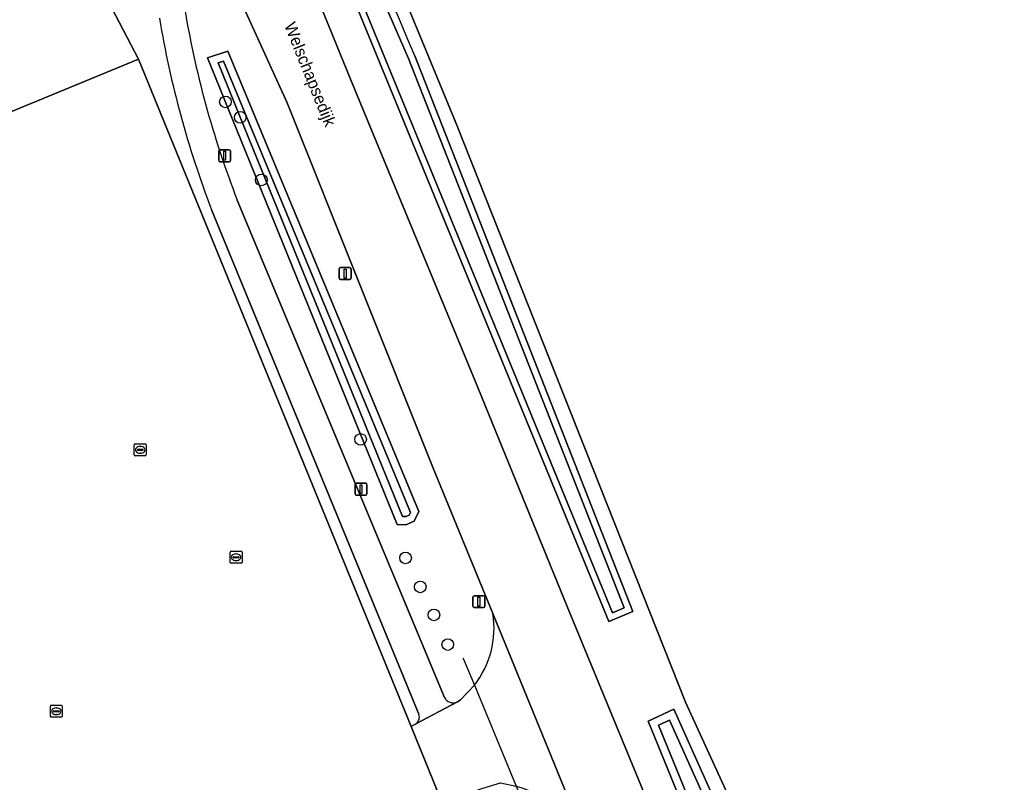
# Model space of a CAD drawing. Extents: x 156061 to 157804, y 383437 to 385640.
# Drawn here: x 157555.9 to 157638, y 383821.9 to 383885.9 of the extents above; entities that cross this region are included whole.
import ezdxf

# ---------------------------------------------------------------- set-up
doc = ezdxf.new("R2010")
doc.units = 0
for name, color, linetype in [('IMGEO_Boom', 7, 'Continuous'), ('IMGEO_Bouwland', 7, 'Continuous'), ('IMGEO_Duiker', 7, 'Continuous'), ('IMGEO_Erf', 7, 'Continuous'), ('IMGEO_Fietspad_gesloten', 7, 'Continuous'), ('IMGEO_Grasland_overig', 7, 'Continuous'), ('IMGEO_Groenvoorziening', 7, 'Continuous'), ('IMGEO_Hek', 7, 'Continuous'), ('IMGEO_Kolk', 7, 'Continuous'), ('IMGEO_Lichtmast', 7, 'Continuous'), ('IMGEO_Oever', 7, 'Continuous'), ('IMGEO_Openbare_ruimte_label', 7, 'Continuous'), ('IMGEO_Rijbaan_lokaal_gesloten', 7, 'Continuous'), ('IMGEO_Waterloop', 7, 'Continuous')]:
    doc.layers.add(name, color=color, linetype=linetype)

msp = doc.modelspace()

# ---------------------------------------------------------------- linework, layer by layer
at = {"layer": 'IMGEO_Boom'}
for centre in [(157573.23, 383879.012), (157574.474, 383877.713), (157576.243, 383872.456), (157584.585, 383850.666), (157588.355, 383840.711), (157589.594, 383838.279), (157590.74, 383835.926), (157591.907, 383833.435)]:
    msp.add_circle(centre, 0.489, dxfattribs=at)
at = {"layer": 'IMGEO_Bouwland'}
msp.add_lwpolyline([(157569.269, 383927.726), (157571.61, 383923.119), (157579.364, 383907.864), (157588.089, 383888.129), (157592.659, 383877.063), (157611.861, 383828.593), (157620.267, 383810.258)], dxfattribs=at)
at = {"layer": 'IMGEO_Duiker'}
msp.add_lwpolyline([(157593.175, 383832.32), (157593.217, 383832.219), (157594.135, 383830.012), (157597.662, 383821.536), (157598.502, 383819.516), (157598.62, 383819.234)], dxfattribs=at)
at = {"layer": 'IMGEO_Erf'}
msp.add_lwpolyline([(157547.624, 383703.184), (157563.901, 383717.144), (157563.393, 383717.746), (157565.034, 383719.104), (157565.113, 383719.606), (157570.669, 383724.172), (157577.494, 383716.583), (157605.408, 383740.892), (157602.352, 383750), (157597.931, 383763.176), (157581.731, 383811.93), (157588.46, 383816.531), (157589.526, 383818.477), (157589.676, 383818.715), (157589.889, 383818.998), (157590.127, 383819.262), (157590.386, 383819.503), (157590.667, 383819.72), (157590.965, 383819.91), (157591.28, 383820.074), (157591.436, 383820.144), (157588.82, 383826.546), (157565.924, 383882.594), (157500, 383855.42)], dxfattribs=at)
at = {"layer": 'IMGEO_Fietspad_gesloten'}
for points in [[(157591.619, 383828.994), (157574.219, 383870.769)], [(157572.089, 383869.901), (157589.47, 383827.582)], [(157589.235, 383826.786), (157592.707, 383828.616)]]:
    msp.add_lwpolyline(points, dxfattribs=at)
for centre, radius, start, end in [((157650.226, 383900.279), 81.535, 189.27321, 201.21866), ((157649.02, 383899.57), 82.454, 189.44953, 201.08955), ((157592.361, 383829.374), 0.834, 207.15129, 294.53155), ((157588.84, 383827.335), 0.676, 305.71255, 21.39149)]:
    msp.add_arc(centre, radius, start, end, dxfattribs=at)
at = {"layer": 'IMGEO_Grasland_overig'}
msp.add_lwpolyline([(157500, 383855.42), (157565.924, 383882.594), (157562.422, 383889.314), (157554.173, 383911.134)], dxfattribs=at)
at = {"layer": 'IMGEO_Groenvoorziening'}
for points in [[(157555.936, 383937.978), (157567.649, 383916.146), (157574.443, 383902.797), (157575.841, 383901.417), (157579.951, 383892.187), (157580.13, 383890.352), (157580.203, 383889.6), (157583.743, 383880.908), (157594.173, 383855.636), (157601.935, 383836.642), (157610.744, 383815.241), (157612.747, 383810.251)], [(157709.127, 383838.303), (157708.901, 383838.826), (157708.521, 383839.482), (157702.798, 383849.357), (157707.546, 383840.384), (157700.202, 383834.337), (157695.919, 383830.811), (157693.54, 383829.055), (157691.043, 383827.496), (157689.841, 383826.746), (157683.073, 383823.26), (157676.592, 383820.429), (157634.606, 383803.387), (157626.262, 383803.732), (157620.267, 383810.258), (157611.861, 383828.593), (157592.659, 383877.063), (157588.089, 383888.129), (157579.364, 383907.864), (157571.61, 383923.119), (157569.269, 383927.726)], [(157554.173, 383911.134), (157562.422, 383889.314), (157565.924, 383882.594), (157588.82, 383826.546), (157589.235, 383826.786)], [(157589.126, 383882.867), (157607.436, 383836.202), (157605.427, 383835.371), (157584.115, 383887.329), (157576.317, 383905.276)], [(157595.701, 383836.038), (157590.677, 383848.249), (157578.419, 383878.917), (157574.359, 383887.856), (157574.182, 383887.793), (157573.057, 383889.421), (157569.032, 383898.551)], [(157574.219, 383870.769), (157591.619, 383828.994)], [(157589.47, 383827.582), (157572.089, 383869.901)], [(157592.707, 383828.616), (157592.966, 383828.799), (157594.135, 383830.012)], [(157614.914, 383811.856), (157608.724, 383827.011), (157610.885, 383827.994), (157618.869, 383810.192)]]:
    msp.add_lwpolyline(points, dxfattribs=at)
msp.add_lwpolyline([(157589.476, 383844.598), (157589.085, 383843.789), (157588.375, 383843.5), (157587.647, 383843.51), (157571.725, 383882.697), (157573.438, 383883.276)], close=True, dxfattribs=at)
for centre, radius, start, end in [((157159.809, 383704.268), 464.985, 22.5876, 28.70083), ((157650.226, 383900.279), 81.535, 189.27321, 201.21866), ((157649.02, 383899.57), 82.454, 189.44953, 201.08955), ((157587.907, 383834.847), 7.885, 322.17817, 8.68693), ((157592.361, 383829.374), 0.834, 207.15129, 294.53155), ((157588.84, 383827.335), 0.676, 305.71255, 21.39149)]:
    msp.add_arc(centre, radius, start, end, dxfattribs=at)
at = {"layer": 'IMGEO_Hek'}
for points in [[(157500, 383855.42), (157565.924, 383882.594)], [(157565.924, 383882.594), (157588.82, 383826.546)], [(157588.82, 383826.546), (157591.436, 383820.144)]]:
    msp.add_lwpolyline(points, dxfattribs=at)
at = {"layer": 'IMGEO_Kolk'}
for p, q in [((157565.576, 383849.361), (157565.576, 383850.213)), ((157565.651, 383850.287), (157566.503, 383850.287)), ((157565.835, 383849.781), (157565.835, 383849.793)), ((157566.273, 383849.744), (157565.875, 383849.744)), ((157565.878, 383849.83), (157566.276, 383849.83)), ((157566.064, 383850.067), (157566.089, 383850.067)), ((157566.319, 383849.793), (157566.319, 383849.781)), ((157566.577, 383850.213), (157566.577, 383849.361)), ((157566.503, 383849.287), (157565.651, 383849.287)), ((157566.087, 383849.507), (157566.062, 383849.507)), ((157573.624, 383840.338), (157573.624, 383841.19)), ((157573.699, 383841.264), (157574.551, 383841.264)), ((157573.883, 383840.758), (157573.883, 383840.77)), ((157574.321, 383840.721), (157573.923, 383840.721)), ((157573.926, 383840.807), (157574.324, 383840.807)), ((157574.112, 383841.044), (157574.137, 383841.044)), ((157574.367, 383840.77), (157574.367, 383840.758)), ((157574.625, 383841.19), (157574.625, 383840.338)), ((157574.551, 383840.264), (157573.699, 383840.264)), ((157574.135, 383840.484), (157574.11, 383840.484)), ((157558.523, 383827.403), (157558.523, 383828.255)), ((157558.598, 383828.329), (157559.45, 383828.329)), ((157558.782, 383827.823), (157558.782, 383827.835)), ((157559.22, 383827.786), (157558.822, 383827.786)), ((157558.825, 383827.872), (157559.223, 383827.872)), ((157559.011, 383828.109), (157559.036, 383828.109)), ((157559.266, 383827.835), (157559.266, 383827.823)), ((157559.524, 383828.255), (157559.524, 383827.403)), ((157559.45, 383827.329), (157558.598, 383827.329)), ((157559.034, 383827.549), (157559.009, 383827.549))]:
    msp.add_line(p, q, dxfattribs=at)
for points in [[(157565.576, 383849.361), (157565.576, 383850.213)], [(157565.651, 383850.287), (157566.503, 383850.287)], [(157566.577, 383850.213), (157566.577, 383849.361)], [(157566.503, 383849.287), (157565.651, 383849.287)], [(157573.624, 383840.338), (157573.624, 383841.19)], [(157573.699, 383841.264), (157574.551, 383841.264)], [(157574.625, 383841.19), (157574.625, 383840.338)], [(157574.551, 383840.264), (157573.699, 383840.264)], [(157558.523, 383827.403), (157558.523, 383828.255)], [(157558.598, 383828.329), (157559.45, 383828.329)], [(157559.524, 383828.255), (157559.524, 383827.403)], [(157559.45, 383827.329), (157558.598, 383827.329)]]:
    msp.add_lwpolyline(points, dxfattribs=at)
for centre, radius, start, end in [((157565.653, 383850.211), 0.0765, 91.55205, 178.44795), ((157565.653, 383850.211), 0.0765, 91.55205, 178.44795), ((157565.875, 383849.79), 0.0403, 85.87752, 175.75265), ((157565.872, 383849.78), 0.0366, 178.93798, 274.71019), ((157566.276, 383849.787), 0.043, 264.86636, 352.45326), ((157566.28, 383849.792), 0.0386, 1.73085, 96.63898), ((157566.501, 383850.211), 0.0765, 1.55205, 88.44795), ((157566.501, 383850.211), 0.0765, 1.55205, 88.44795), ((157565.653, 383849.363), 0.0765, 181.55205, 268.44795), ((157565.653, 383849.363), 0.0765, 181.55205, 268.44795), ((157566.501, 383849.363), 0.0765, 271.55205, 358.44795), ((157566.501, 383849.363), 0.0765, 271.55205, 358.44795), ((157573.701, 383841.188), 0.0765, 91.55205, 178.44795), ((157573.701, 383841.188), 0.0765, 91.55205, 178.44795), ((157573.923, 383840.767), 0.0403, 85.87752, 175.75265), ((157573.92, 383840.757), 0.0366, 178.93798, 274.71019), ((157574.324, 383840.764), 0.043, 264.86636, 352.45326), ((157574.328, 383840.769), 0.0386, 1.73085, 96.63898), ((157574.549, 383841.188), 0.0765, 1.55205, 88.44795), ((157574.549, 383841.188), 0.0765, 1.55205, 88.44795), ((157573.701, 383840.34), 0.0765, 181.55205, 268.44795), ((157573.701, 383840.34), 0.0765, 181.55205, 268.44795), ((157574.549, 383840.34), 0.0765, 271.55205, 358.44795), ((157574.549, 383840.34), 0.0765, 271.55205, 358.44795), ((157558.6, 383828.253), 0.0765, 91.55205, 178.44795), ((157558.6, 383828.253), 0.0765, 91.55205, 178.44795), ((157558.822, 383827.832), 0.0403, 85.87752, 175.75265), ((157558.819, 383827.822), 0.0366, 178.93798, 274.71019), ((157559.223, 383827.829), 0.043, 264.86636, 352.45326), ((157559.227, 383827.834), 0.0386, 1.73085, 96.63898), ((157559.448, 383828.253), 0.0765, 1.55205, 88.44795), ((157559.448, 383828.253), 0.0765, 1.55205, 88.44795), ((157558.6, 383827.405), 0.0765, 181.55205, 268.44795), ((157558.6, 383827.405), 0.0765, 181.55205, 268.44795), ((157559.448, 383827.405), 0.0765, 271.55205, 358.44795), ((157559.448, 383827.405), 0.0765, 271.55205, 358.44795)]:
    msp.add_arc(centre, radius, start, end, dxfattribs=at)
for centre, major_axis, ratio, start_param, end_param in [((157566.063, 383849.787), (-0.387, 0.002), 0.722429, 4.712389, 7.853982), ((157566.088, 383849.787), (-0.39, 0.002), 0.717154, 1.570796, 4.712389), ((157574.111, 383840.764), (-0.387, 0.002), 0.722429, 4.712389, 7.853982), ((157574.136, 383840.764), (-0.39, 0.002), 0.717154, 1.570796, 4.712389), ((157559.01, 383827.829), (-0.387, 0.002), 0.722429, 4.712389, 7.853982), ((157559.035, 383827.829), (-0.39, 0.002), 0.717154, 1.570796, 4.712389)]:
    msp.add_ellipse(centre, major_axis=major_axis, ratio=ratio, start_param=start_param, end_param=end_param, dxfattribs=at)
at = {"layer": 'IMGEO_Lichtmast'}
for p, q in [((157572.664, 383874.086), (157572.664, 383874.886)), ((157572.664, 383874.886), (157572.664, 383874.086)), ((157572.764, 383874.986), (157573.554, 383874.986)), ((157573.554, 383874.986), (157572.764, 383874.986)), ((157573.654, 383874.886), (157573.654, 383874.086)), ((157573.654, 383874.086), (157573.654, 383874.886)), ((157573.554, 383873.986), (157572.764, 383873.986)), ((157572.764, 383873.986), (157573.554, 383873.986)), ((157582.787, 383864.191), (157582.787, 383864.991)), ((157582.787, 383864.991), (157582.787, 383864.191)), ((157582.887, 383865.091), (157583.677, 383865.091)), ((157583.677, 383865.091), (157582.887, 383865.091)), ((157583.777, 383864.991), (157583.777, 383864.191)), ((157583.777, 383864.191), (157583.777, 383864.991)), ((157583.677, 383864.091), (157582.887, 383864.091)), ((157582.887, 383864.091), (157583.677, 383864.091)), ((157584.119, 383846.083), (157584.119, 383846.883)), ((157584.119, 383846.883), (157584.119, 383846.083)), ((157584.219, 383846.983), (157585.009, 383846.983)), ((157585.009, 383846.983), (157584.219, 383846.983)), ((157585.109, 383846.883), (157585.109, 383846.083)), ((157585.109, 383846.083), (157585.109, 383846.883)), ((157585.009, 383845.983), (157584.219, 383845.983)), ((157584.219, 383845.983), (157585.009, 383845.983)), ((157594.022, 383836.639), (157594.022, 383837.439)), ((157594.022, 383837.439), (157594.022, 383836.639)), ((157594.122, 383837.539), (157594.912, 383837.539)), ((157594.912, 383837.539), (157594.122, 383837.539)), ((157595.012, 383837.439), (157595.012, 383836.639)), ((157595.012, 383836.639), (157595.012, 383837.439)), ((157594.912, 383836.539), (157594.122, 383836.539)), ((157594.122, 383836.539), (157594.912, 383836.539))]:
    msp.add_line(p, q, dxfattribs=at)
for points in [[(157573.084, 383874.861), (157573.234, 383874.861), (157573.234, 383874.111), (157573.084, 383874.111), (157573.084, 383874.861)], [(157583.207, 383864.966), (157583.357, 383864.966), (157583.357, 383864.216), (157583.207, 383864.216), (157583.207, 383864.966)], [(157584.539, 383846.858), (157584.689, 383846.858), (157584.689, 383846.108), (157584.539, 383846.108), (157584.539, 383846.858)], [(157594.442, 383837.414), (157594.592, 383837.414), (157594.592, 383836.664), (157594.442, 383836.664), (157594.442, 383837.414)]]:
    msp.add_lwpolyline(points, dxfattribs=at)
for centre, start, end in [((157572.764, 383874.886), 90, 180), ((157572.764, 383874.886), 90, 180), ((157573.554, 383874.886), 0, 90), ((157573.554, 383874.886), 360, 90), ((157572.764, 383874.086), 180, 270), ((157572.764, 383874.086), 180, 270), ((157573.554, 383874.086), 270, 0), ((157573.554, 383874.086), 270, 0), ((157582.887, 383864.991), 90, 180), ((157582.887, 383864.991), 90, 180), ((157583.677, 383864.991), 0, 90), ((157583.677, 383864.991), 360, 90), ((157582.887, 383864.191), 180, 270), ((157582.887, 383864.191), 180, 270), ((157583.677, 383864.191), 270, 0), ((157583.677, 383864.191), 270, 0), ((157584.219, 383846.883), 90, 180), ((157584.219, 383846.883), 90, 180), ((157585.009, 383846.883), 0, 90), ((157585.009, 383846.883), 360, 90), ((157584.219, 383846.083), 180, 270), ((157584.219, 383846.083), 180, 270), ((157585.009, 383846.083), 270, 0), ((157585.009, 383846.083), 270, 0), ((157594.122, 383837.439), 90, 180), ((157594.122, 383837.439), 90, 180), ((157594.912, 383837.439), 0, 90), ((157594.912, 383837.439), 360, 90), ((157594.122, 383836.639), 180, 270), ((157594.122, 383836.639), 180, 270), ((157594.912, 383836.639), 270, 0), ((157594.912, 383836.639), 270, 0)]:
    msp.add_arc(centre, 0.1, start, end, dxfattribs=at)
at = {"layer": 'IMGEO_Oever'}
for points in [[(157566.057, 383926.043), (157567.443, 383926.809), (157575.014, 383912.342), (157582.071, 383897.619), (157588.606, 383882.657), (157606.713, 383836.509), (157605.732, 383836.104), (157584.631, 383887.547), (157576.827, 383905.507), (157573.431, 383912.453), (157569.84, 383919.3)], [(157573.438, 383883.276), (157571.725, 383882.697), (157587.647, 383843.51), (157588.375, 383843.5), (157589.085, 383843.789), (157589.476, 383844.598)], [(157588.09, 383844.201), (157574.474, 383877.713), (157572.615, 383882.289), (157573.058, 383882.439), (157588.776, 383844.536), (157588.662, 383844.296), (157588.422, 383844.184)]]:
    msp.add_lwpolyline(points, close=True, dxfattribs=at)
for points in [[(157576.317, 383905.276), (157584.115, 383887.329), (157605.427, 383835.371), (157607.436, 383836.202), (157589.126, 383882.867)], [(157618.869, 383810.192), (157610.885, 383827.994), (157608.724, 383827.011), (157614.914, 383811.856)], [(157615.568, 383812.076), (157609.612, 383826.658), (157610.54, 383827.081), (157618.255, 383809.88)]]:
    msp.add_lwpolyline(points, dxfattribs=at)
msp.add_arc((157159.809, 383704.268), 464.985, 22.5876, 28.70083, dxfattribs=at)
at = {"layer": 'IMGEO_Rijbaan_lokaal_gesloten'}
for points in [[(157610.744, 383815.241), (157601.935, 383836.642), (157594.173, 383855.636), (157583.743, 383880.908), (157580.203, 383889.6), (157580.13, 383890.352), (157578.665, 383893.608), (157577.707, 383893.165), (157573.988, 383891.504), (157573.001, 383891.061), (157574.359, 383887.856), (157578.419, 383878.917), (157590.677, 383848.249), (157595.701, 383836.038), (157602.956, 383818.231)], [(157594.135, 383830.012), (157592.966, 383828.799), (157592.707, 383828.616), (157589.235, 383826.786), (157588.82, 383826.546), (157591.436, 383820.144), (157594.764, 383821.334), (157596.342, 383821.812), (157597.662, 383821.536), (157598.129, 383821.397), (157599.041, 383821.057), (157599.919, 383820.637), (157600.756, 383820.14), (157601.546, 383819.57), (157602.281, 383818.932), (157602.956, 383818.231), (157595.701, 383836.038)]]:
    msp.add_lwpolyline(points, dxfattribs=at)
msp.add_arc((157587.907, 383834.847), 7.885, 322.17817, 8.68693, dxfattribs=at)
at = {"layer": 'IMGEO_Waterloop'}
for points in [[(157566.057, 383926.043), (157569.84, 383919.3), (157573.431, 383912.453), (157576.827, 383905.507), (157584.631, 383887.547), (157605.732, 383836.104), (157606.713, 383836.509), (157588.606, 383882.657), (157582.071, 383897.619), (157575.014, 383912.342), (157567.443, 383926.809)], [(157588.09, 383844.201), (157588.422, 383844.184), (157588.662, 383844.296), (157588.776, 383844.536), (157573.058, 383882.439), (157572.615, 383882.289), (157574.474, 383877.713)]]:
    msp.add_lwpolyline(points, close=True, dxfattribs=at)
msp.add_lwpolyline([(157618.255, 383809.88), (157610.54, 383827.081), (157609.612, 383826.658), (157615.568, 383812.076)], dxfattribs=at)

# ---------------------------------------------------------------- texts
at = {"layer": 'IMGEO_Openbare_ruimte_label'}
msp.add_text('Welschapsedijk', height=1, rotation=291.97171, dxfattribs=at).set_placement((157578.148, 383885.449))

doc.saveas('drawing.dxf')
